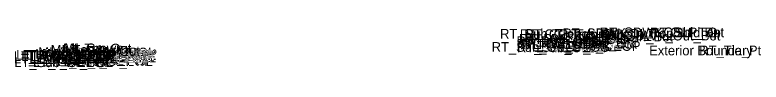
# Model space of a CAD drawing. Extents: x -26 to 6300, y -10 to 9528.
# Drawn here: x 3130.1 to 3207.1, y 1501.3 to 1505.7 of the extents above; entities that cross this region are included whole.
import ezdxf

# ---------------------------------------------------------------- set-up
doc = ezdxf.new("R2010")
doc.units = 0
doc.layers.add('Default', color=7, linetype='Continuous')

msp = doc.modelspace()

# ---------------------------------------------------------------- texts
at = {"layer": 'Default'}
for s, p in [('RT_Sub_Trench_Out_DLT', (3180.181, 1504.548)), ('RT_CG_Top_Face', (3182.225, 1504.509)), ('RT_CG_Top_BOC', (3182.694, 1504.509)), ('RT_SDWK_In_Top', (3186.62, 1504.599)), ('RT_SDWK_Out_Top', (3190.462, 1504.699)), ('RT_SDWK_Out_Bot', (3190.711, 1504.365)), ('RT_Shld_O', (3195.632, 1504.689)), ('CSLP_Pnt', (3197.035, 1504.699)), ('RT_PV2_OEOT', (3181.873, 1503.779)), ('RT_PV3_OEOT', (3181.873, 1503.529)), ('RT_PV1_OEOT', (3182.112, 1504.029)), ('RT_CG1_Shelf_Out', (3182.36, 1503.535)), ('RT_CG_Top_Gut', (3182.752, 1504.009)), ('RT_CG_Bot_BOC', (3182.97, 1503.52)), ('RT_SDWK_In_Bot', (3186.869, 1504.265)), ('MI_Top In', (3133.839, 1502.908)), ('MI_Top Out', (3135.095, 1503.028)), ('MI_Crown', (3135.239, 1503.052)), ('MI_Face Out', (3135.307, 1502.778)), ('RT_Sub_OEOT_CG', (3179.318, 1503.195)), ('RT_Sub_OEOT', (3181.92, 1503.154)), ('RT_CG_Bot_IE', (3182.221, 1503.445)), ('RT_Sub_OEOP', (3185.154, 1503.292)), ('Exterior Boundary', (3195.56, 1502.829)), ('RT_Tie_Pt', (3200.722, 1502.829)), ('LT_PV2_OEEOP', (3130.035, 1502.241)), ('LT_PV3_OEEOP', (3130.035, 1501.991)), ('LT_PV1_OEEOP', (3130.275, 1502.366)), ('LT_PV2_IEEOP', (3130.796, 1502.241)), ('LT_PV1_IEEOP', (3131.035, 1502.366)), ('LT_PV2_PGL1', (3131.635, 1502.241)), ('LT_PV3_PGL1', (3131.635, 1501.991)), ('LT_PV2_PGL', (3132.014, 1502.241)), ('LT_PV1_PGL', (3132.253, 1502.491)), ('MI_Face In', (3132.551, 1502.658)), ('MI_Bot In', (3133.721, 1502.491)), ('RT_PV2_OEEOP', (3133.917, 1502.361)), ('RT_PV3_OEEOP', (3133.917, 1502.111)), ('RT_PV1_OEEOP', (3134.157, 1502.486)), ('RT_PV2_IEEOP', (3134.678, 1502.361)), ('RT_PV1_IEEOP', (3134.917, 1502.486)), ('RT_PV2_PGL1', (3135.516, 1502.361)), ('RT_PV3_PGL1', (3135.516, 1502.111)), ('RT_PV2_PGL', (3135.895, 1502.361)), ('RT_PV1_PGL', (3136.135, 1502.611)), ('MI_Bot Out', (3136.498, 1502.611)), ('LT_Sub_OEEOP', (3130.082, 1501.616)), ('LT_PV4_PGL', (3132.014, 1501.616)), ('RT_Sub_OEEOP', (3133.964, 1501.736)), ('RT_PV4_PGL', (3135.895, 1501.736))]:
    msp.add_text(s, height=1, dxfattribs=at).set_placement(p)

doc.saveas('drawing.dxf')
